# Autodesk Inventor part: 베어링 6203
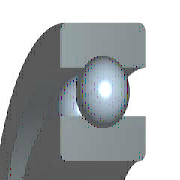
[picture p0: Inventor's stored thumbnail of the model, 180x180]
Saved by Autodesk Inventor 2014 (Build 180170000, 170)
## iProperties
Created: 2012-02
Part Number: 베어링 6203
Material: 강철, 연강
Description: 깊은 그루브 볼 베어링
Document SubType Name: Modeling
Standard: KS B 2023
Designer: mduedu
Standards Organization: KS
Language: ko-KR
Size Designation: 6203 - 17 x 40 x 12
Categories: <MemberInstance><Categories><Category DisplayName="샤프트 부품" InternalName="7f7aeb1f-a693-4053-b835-cee3144e0d98" Mnemonic="SHFT"><Category DisplayName="베어링" Inter
Density: 7.86 g/cm^3
Appearance: 노란색
Mass: 58.8203 g
Surface Area: 64.3582 cm^2
Volume: 7.4835 cm^3
IsCustomPart: 1
Author: mduedu
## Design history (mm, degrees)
sketch "스케치" dims "d0" = 5.98 (= -0.26 x WD + 0.26 x BD)
  geometry: L1 (3.01, 14.25)-(8.99, 14.25); L2 (6, 14.25)-(6, 11.26); L3 (6, 14.25)-(6, 17.24); L4 (3.778, 12.249)-(0, 12.249); L5 (0, 8.5)-(12, 8.5); L6 (3.778, 16.251)-(0, 16.251); L7 (0, 20)-(12, 20); L8 (12, 8.5)-(12, 12.249); L9 (8.222, 12.249)-(12, 12.249); L10 (8.222, 16.251)-(12, 16.251); L11 (12, 20)-(12, 16.251); L12 (-1.4, 0)-(8.4, 0) reference; L13 (0, -0.3)-(0, 5.3) reference
  constraints: 22 end point, 4 point on line, 2 collinear, 2 perpendicular, 2 symmetric about line, 1 midpoint, 1 parallel, 14 other
  dimensions: "d9" = 17 diameter of L5 L12 (= WD); "d11" = 40 diameter of L7 L12 (= BD); "d12" = 12 distance between parallel lines of L8 L13 (= KB); "d13" = 24.498 diameter of L9 L12 (= 0.326 x BD + 0.674 x WD)
revolve "본체" stored, may be unused: angle "d6" = 90 deg
revolve "볼" stored, may be unused: angle "d7" = 90 deg
pattern_circular "IDS_ARRAYBALL[SIMPL:T]" dims angle "d3" = 360 deg
body "Solid1"
fillet "모깎기1" dims "d1" = 0.6 (= KRS)
other parameters: "WD" = 17 [user parameter; used in 5 equation terms], "BD" = 40 [user parameter; used in 5 equation terms], "KB" = 12 [user parameter; used in 1 equation term], "KRS" = 0.6 [user parameter; used in 1 equation term], "d4" = 0, "d5" = 0, "d8" = 0, "d14" = 0, "d15" = 0, "BBA" = 0 [user parameter], "BC0" = 4750000 [user parameter], "BC" = 9560000 [user parameter], "WR" = 8.5 (= 0.5 x WD) [user parameter]
